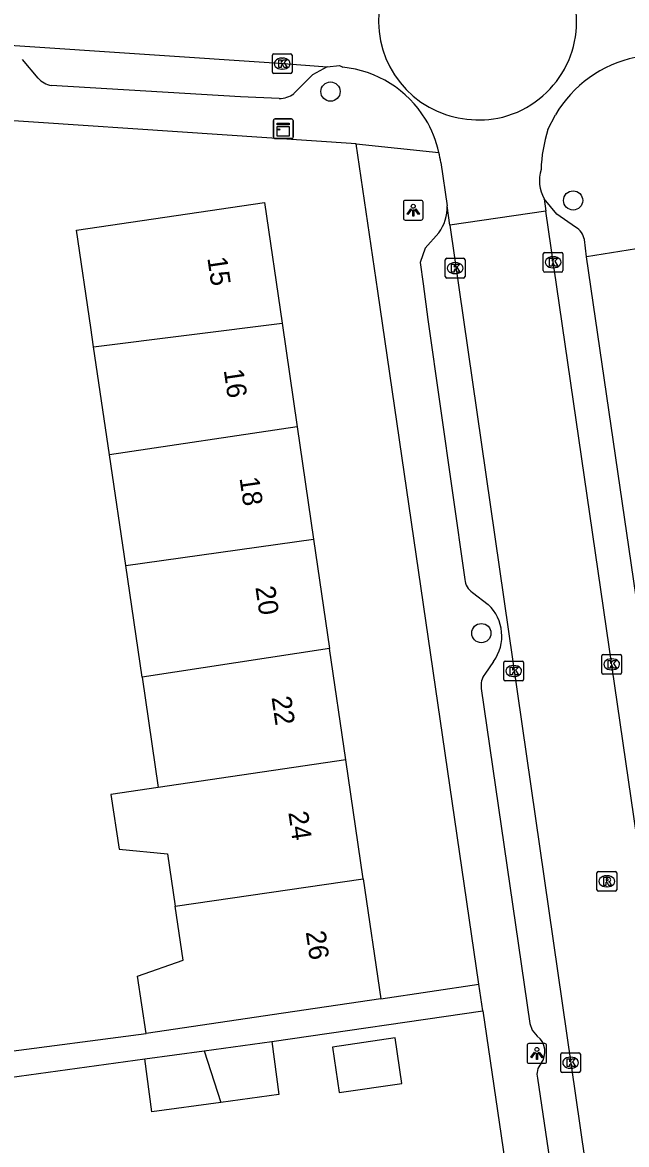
# Model space of a CAD drawing. Extents: x 159053 to 160041, y 380450 to 381422.
# Drawn here: x 159474.1 to 159504.8, y 381120.2 to 381177.1 of the extents above; entities that cross this region are included whole.
import ezdxf

# ---------------------------------------------------------------- set-up
doc = ezdxf.new("R2010")
doc.units = 0
for name, color, linetype in [('IMGEO_Boom', 7, 'Continuous'), ('IMGEO_Kast', 7, 'Continuous'), ('IMGEO_Kolk', 7, 'Continuous'), ('IMGEO_Lichtpunt', 7, 'Continuous'), ('IMGEO_Pand', 7, 'Continuous'), ('IMGEO_Pand_nummerreeks', 7, 'Continuous'), ('IMGEO_Rijbaan_lokaal_open', 7, 'Continuous'), ('IMGEO_Rioolput', 7, 'Continuous'), ('IMGEO_Voetpad_open', 7, 'Continuous')]:
    doc.layers.add(name, color=color, linetype=linetype)

msp = doc.modelspace()

# ---------------------------------------------------------------- linework, layer by layer
at = {"layer": 'IMGEO_Boom'}
for centre in [(159489.765, 381173.623), (159502.088, 381168.096), (159497.428, 381146.127)]:
    msp.add_circle(centre, 0.489, dxfattribs=at)
at = {"layer": 'IMGEO_Kast'}
for p, q in [((159486.868, 381171.309), (159486.868, 381172.15)), ((159486.868, 381172.15), (159486.868, 381171.309)), ((159486.943, 381172.234), (159487.784, 381172.234)), ((159487.784, 381172.234), (159486.943, 381172.234)), ((159487.868, 381172.159), (159487.868, 381171.318)), ((159487.868, 381171.318), (159487.868, 381172.159)), ((159487.793, 381171.234), (159486.952, 381171.234)), ((159486.952, 381171.234), (159487.793, 381171.234))]:
    msp.add_line(p, q, dxfattribs=at)
for points in [[(159487.063, 381172.024), (159487.663, 381172.024), (159487.663, 381171.939), (159487.063, 381171.939), (159487.063, 381172.024)], [(159487.063, 381171.849), (159487.663, 381171.849), (159487.663, 381171.36), (159487.063, 381171.36), (159487.063, 381171.849)]]:
    msp.add_lwpolyline(points, dxfattribs=at)
msp.add_circle((159487.147, 381171.698), 0.0377, dxfattribs=at)
for centre, start, end in [((159486.946, 381172.156), 92.4484, 184.2845), ((159486.946, 381172.156), 92.4484, 184.2845), ((159487.79, 381172.156), 2.4484, 94.2845), ((159487.79, 381172.156), 2.4484, 94.2845), ((159486.946, 381171.312), 182.4484, 274.2845), ((159486.946, 381171.312), 182.4484, 274.2845), ((159487.79, 381171.312), 272.4484, 4.2845), ((159487.79, 381171.312), 272.4484, 4.2845)]:
    msp.add_arc(centre, 0.0779, start, end, dxfattribs=at)
at = {"layer": 'IMGEO_Kolk'}
for p, q in [((159486.812, 381174.617), (159486.812, 381175.469)), ((159486.887, 381175.543), (159487.739, 381175.543)), ((159487.3, 381175.323), (159487.325, 381175.323)), ((159487.813, 381175.469), (159487.813, 381174.617)), ((159487.323, 381174.763), (159487.298, 381174.763)), ((159487.739, 381174.543), (159486.887, 381174.543)), ((159495.597, 381164.232), (159495.597, 381165.084)), ((159495.672, 381165.158), (159496.524, 381165.158)), ((159496.598, 381165.084), (159496.598, 381164.232)), ((159500.572, 381164.531), (159500.572, 381165.383)), ((159500.647, 381165.457), (159501.499, 381165.457)), ((159501.06, 381165.237), (159501.085, 381165.237)), ((159501.573, 381165.383), (159501.573, 381164.531)), ((159496.085, 381164.938), (159496.11, 381164.938)), ((159501.083, 381164.677), (159501.058, 381164.677)), ((159496.524, 381164.158), (159495.672, 381164.158)), ((159496.108, 381164.378), (159496.083, 381164.378)), ((159501.499, 381164.457), (159500.647, 381164.457)), ((159498.569, 381143.777), (159498.569, 381144.629)), ((159498.644, 381144.703), (159499.496, 381144.703)), ((159499.57, 381144.629), (159499.57, 381143.777)), ((159503.547, 381144.116), (159503.547, 381144.968)), ((159503.622, 381145.042), (159504.474, 381145.042)), ((159504.035, 381144.822), (159504.06, 381144.822)), ((159504.548, 381144.968), (159504.548, 381144.116)), ((159499.057, 381144.483), (159499.082, 381144.483)), ((159504.474, 381144.042), (159503.622, 381144.042)), ((159504.058, 381144.262), (159504.033, 381144.262)), ((159499.496, 381143.703), (159498.644, 381143.703)), ((159499.08, 381143.923), (159499.055, 381143.923)), ((159501.458, 381123.888), (159501.458, 381124.74)), ((159501.533, 381124.814), (159502.385, 381124.814)), ((159501.946, 381124.594), (159501.971, 381124.594)), ((159502.459, 381124.74), (159502.459, 381123.888)), ((159501.969, 381124.034), (159501.944, 381124.034)), ((159502.385, 381123.814), (159501.533, 381123.814))]:
    msp.add_line(p, q, dxfattribs=at)
for points in [[(159486.812, 381174.617), (159486.812, 381175.469)], [(159486.887, 381175.543), (159487.739, 381175.543)], [(159487.813, 381175.469), (159487.813, 381174.617)], [(159487.133, 381175.243), (159487.256, 381175.243), (159487.256, 381175.092), (159487.386, 381175.243), (159487.55, 381175.243), (159487.404, 381175.092), (159487.557, 381174.843), (159487.405, 381174.843), (159487.32, 381175.007), (159487.256, 381174.94), (159487.256, 381174.843), (159487.133, 381174.843), (159487.133, 381175.243)], [(159487.739, 381174.543), (159486.887, 381174.543)], [(159495.597, 381164.232), (159495.597, 381165.084)], [(159495.672, 381165.158), (159496.524, 381165.158)], [(159496.598, 381165.084), (159496.598, 381164.232)], [(159500.572, 381164.531), (159500.572, 381165.383)], [(159500.647, 381165.457), (159501.499, 381165.457)], [(159500.893, 381165.157), (159501.016, 381165.157), (159501.016, 381165.006), (159501.146, 381165.157), (159501.31, 381165.157), (159501.164, 381165.006), (159501.317, 381164.757), (159501.165, 381164.757), (159501.08, 381164.921), (159501.016, 381164.854), (159501.016, 381164.757), (159500.893, 381164.757), (159500.893, 381165.157)], [(159501.573, 381165.383), (159501.573, 381164.531)], [(159495.918, 381164.858), (159496.041, 381164.858), (159496.041, 381164.707), (159496.171, 381164.858), (159496.335, 381164.858), (159496.189, 381164.707), (159496.342, 381164.458), (159496.19, 381164.458), (159496.105, 381164.622), (159496.041, 381164.555), (159496.041, 381164.458), (159495.918, 381164.458), (159495.918, 381164.858)], [(159496.524, 381164.158), (159495.672, 381164.158)], [(159501.499, 381164.457), (159500.647, 381164.457)], [(159498.569, 381143.777), (159498.569, 381144.629)], [(159498.644, 381144.703), (159499.496, 381144.703)], [(159499.57, 381144.629), (159499.57, 381143.777)], [(159503.547, 381144.116), (159503.547, 381144.968)], [(159503.622, 381145.042), (159504.474, 381145.042)], [(159503.868, 381144.742), (159503.991, 381144.742), (159503.991, 381144.591), (159504.121, 381144.742), (159504.285, 381144.742), (159504.139, 381144.591), (159504.292, 381144.342), (159504.14, 381144.342), (159504.055, 381144.506), (159503.991, 381144.439), (159503.991, 381144.342), (159503.868, 381144.342), (159503.868, 381144.742)], [(159504.548, 381144.968), (159504.548, 381144.116)], [(159498.89, 381144.403), (159499.013, 381144.403), (159499.013, 381144.252), (159499.143, 381144.403), (159499.307, 381144.403), (159499.161, 381144.252), (159499.314, 381144.003), (159499.162, 381144.003), (159499.077, 381144.167), (159499.013, 381144.1), (159499.013, 381144.003), (159498.89, 381144.003), (159498.89, 381144.403)], [(159504.474, 381144.042), (159503.622, 381144.042)], [(159499.496, 381143.703), (159498.644, 381143.703)], [(159501.458, 381123.888), (159501.458, 381124.74)], [(159501.533, 381124.814), (159502.385, 381124.814)], [(159502.459, 381124.74), (159502.459, 381123.888)], [(159501.779, 381124.514), (159501.902, 381124.514), (159501.902, 381124.363), (159502.032, 381124.514), (159502.196, 381124.514), (159502.05, 381124.363), (159502.203, 381124.114), (159502.051, 381124.114), (159501.966, 381124.278), (159501.902, 381124.211), (159501.902, 381124.114), (159501.779, 381124.114), (159501.779, 381124.514)], [(159502.385, 381123.814), (159501.533, 381123.814)]]:
    msp.add_lwpolyline(points, dxfattribs=at)
for centre, start, end in [((159486.889, 381175.467), 91.552, 178.448), ((159486.889, 381175.467), 91.552, 178.448), ((159487.737, 381175.467), 1.552, 88.448), ((159487.737, 381175.467), 1.552, 88.448), ((159486.889, 381174.619), 181.552, 268.448), ((159486.889, 381174.619), 181.552, 268.448), ((159487.737, 381174.619), 271.552, 358.448), ((159487.737, 381174.619), 271.552, 358.448), ((159495.674, 381165.082), 91.552, 178.448), ((159495.674, 381165.082), 91.552, 178.448), ((159496.522, 381165.082), 1.552, 88.448), ((159496.522, 381165.082), 1.552, 88.448), ((159500.649, 381165.381), 91.552, 178.448), ((159500.649, 381165.381), 91.552, 178.448), ((159501.497, 381165.381), 1.552, 88.448), ((159501.497, 381165.381), 1.552, 88.448), ((159500.649, 381164.533), 181.552, 268.448), ((159500.649, 381164.533), 181.552, 268.448), ((159501.497, 381164.533), 271.552, 358.448), ((159501.497, 381164.533), 271.552, 358.448), ((159495.674, 381164.234), 181.552, 268.448), ((159495.674, 381164.234), 181.552, 268.448), ((159496.522, 381164.234), 271.552, 358.448), ((159496.522, 381164.234), 271.552, 358.448), ((159498.646, 381144.627), 91.552, 178.448), ((159498.646, 381144.627), 91.552, 178.448), ((159499.494, 381144.627), 1.552, 88.448), ((159499.494, 381144.627), 1.552, 88.448), ((159503.624, 381144.966), 91.552, 178.448), ((159503.624, 381144.966), 91.552, 178.448), ((159504.472, 381144.966), 1.552, 88.448), ((159504.472, 381144.966), 1.552, 88.448), ((159503.624, 381144.118), 181.552, 268.448), ((159503.624, 381144.118), 181.552, 268.448), ((159504.472, 381144.118), 271.552, 358.448), ((159504.472, 381144.118), 271.552, 358.448), ((159498.646, 381143.779), 181.552, 268.448), ((159498.646, 381143.779), 181.552, 268.448), ((159499.494, 381143.779), 271.552, 358.448), ((159499.494, 381143.779), 271.552, 358.448), ((159501.535, 381124.738), 91.552, 178.448), ((159501.535, 381124.738), 91.552, 178.448), ((159502.383, 381124.738), 1.552, 88.448), ((159502.383, 381124.738), 1.552, 88.448), ((159501.535, 381123.89), 181.552, 268.448), ((159501.535, 381123.89), 181.552, 268.448), ((159502.383, 381123.89), 271.552, 358.448), ((159502.383, 381123.89), 271.552, 358.448)]:
    msp.add_arc(centre, 0.0765, start, end, dxfattribs=at)
for centre, major_axis, ratio, start_param, end_param in [((159487.299, 381175.043), (-0.387, 0.002), 0.722429, 4.712389, 7.853982), ((159487.324, 381175.043), (-0.39, 0.002), 0.717154, 1.570796, 4.712389), ((159501.059, 381164.957), (-0.387, 0.002), 0.722429, 4.712389, 7.853982), ((159501.084, 381164.957), (-0.39, 0.002), 0.717154, 1.570796, 4.712389), ((159496.084, 381164.658), (-0.387, 0.002), 0.722429, 4.712389, 7.853982), ((159496.109, 381164.658), (-0.39, 0.002), 0.717154, 1.570796, 4.712389), ((159504.034, 381144.542), (-0.387, 0.002), 0.722429, 4.712389, 7.853982), ((159504.059, 381144.542), (-0.39, 0.002), 0.717154, 1.570796, 4.712389), ((159499.056, 381144.203), (-0.387, 0.002), 0.722429, 4.712389, 7.853982), ((159499.081, 381144.203), (-0.39, 0.002), 0.717154, 1.570796, 4.712389), ((159501.945, 381124.314), (-0.387, 0.002), 0.722429, 4.712389, 7.853982), ((159501.97, 381124.314), (-0.39, 0.002), 0.717154, 1.570796, 4.712389)]:
    msp.add_ellipse(centre, major_axis=major_axis, ratio=ratio, start_param=start_param, end_param=end_param, dxfattribs=at)
at = {"layer": 'IMGEO_Lichtpunt'}
for p, q in [((159493.469, 381168.003), (159493.469, 381167.196)), ((159493.469, 381168.003), (159493.469, 381167.196)), ((159494.371, 381168.098), (159493.563, 381168.098)), ((159494.371, 381168.098), (159493.563, 381168.098)), ((159494.465, 381167.196), (159494.465, 381168.003)), ((159494.465, 381167.196), (159494.465, 381168.003)), ((159493.563, 381167.102), (159494.371, 381167.102)), ((159493.563, 381167.102), (159494.371, 381167.102)), ((159499.748, 381125.19), (159499.748, 381124.383)), ((159499.748, 381125.19), (159499.748, 381124.383)), ((159500.65, 381125.285), (159499.842, 381125.285)), ((159500.65, 381125.285), (159499.842, 381125.285)), ((159500.744, 381124.383), (159500.744, 381125.19)), ((159500.744, 381124.383), (159500.744, 381125.19)), ((159499.842, 381124.289), (159500.65, 381124.289)), ((159499.842, 381124.289), (159500.65, 381124.289))]:
    msp.add_line(p, q, dxfattribs=at)
for points in [[(159493.843, 381167.667), (159493.882, 381167.639), (159493.694, 381167.377), (159493.656, 381167.404), (159493.843, 381167.667)], [(159493.945, 381167.619), (159493.992, 381167.619), (159493.992, 381167.297), (159493.945, 381167.297), (159493.945, 381167.619)], [(159494.055, 381167.639), (159494.093, 381167.666), (159494.28, 381167.404), (159494.241, 381167.376), (159494.055, 381167.639)], [(159500.122, 381124.854), (159500.161, 381124.826), (159499.973, 381124.564), (159499.935, 381124.591), (159500.122, 381124.854)], [(159500.224, 381124.806), (159500.271, 381124.806), (159500.271, 381124.484), (159500.224, 381124.484), (159500.224, 381124.806)], [(159500.334, 381124.826), (159500.372, 381124.853), (159500.559, 381124.591), (159500.52, 381124.563), (159500.334, 381124.826)]]:
    msp.add_lwpolyline(points, dxfattribs=at)
for centre in [(159493.968, 381167.801), (159500.247, 381124.988)]:
    msp.add_circle(centre, 0.0994, dxfattribs=at)
for centre, start, end in [((159493.563, 381168.003), 90, 180), ((159493.563, 381168.003), 90, 180), ((159494.371, 381168.003), 0, 90), ((159494.371, 381168.003), 0, 90), ((159493.563, 381167.196), 180, 270), ((159493.563, 381167.196), 180, 270), ((159494.371, 381167.196), 270, 0), ((159494.371, 381167.196), 270, 360), ((159499.842, 381125.19), 90, 180), ((159499.842, 381125.19), 90, 180), ((159500.65, 381125.19), 0, 90), ((159500.65, 381125.19), 0, 90), ((159499.842, 381124.383), 180, 270), ((159499.842, 381124.383), 180, 270), ((159500.65, 381124.383), 270, 0), ((159500.65, 381124.383), 270, 360)]:
    msp.add_arc(centre, 0.0946, start, end, dxfattribs=at)
at = {"layer": 'IMGEO_Pand'}
for points in [[(159477.731, 381160.668), (159477.587, 381161.646), (159476.861, 381166.592), (159486.412, 381167.988), (159487.308, 381161.857)], [(159477.731, 381160.668), (159487.308, 381161.857)], [(159487.308, 381161.857), (159488.076, 381156.599)], [(159478.537, 381155.178), (159477.731, 381160.668)], [(159488.076, 381156.599), (159478.537, 381155.178)], [(159488.076, 381156.599), (159488.908, 381150.9)], [(159479.362, 381149.557), (159478.537, 381155.178)], [(159479.362, 381149.557), (159488.908, 381150.9)], [(159488.908, 381150.9), (159489.72, 381145.339)], [(159480.194, 381143.889), (159479.362, 381149.557)], [(159489.72, 381145.339), (159480.194, 381143.889)], [(159490.544, 381139.699), (159489.72, 381145.339)], [(159480.194, 381143.889), (159481.016, 381138.293)], [(159490.544, 381139.699), (159481.016, 381138.293)], [(159491.427, 381133.657), (159490.544, 381139.699)], [(159481.016, 381138.293), (159478.614, 381137.938), (159479.023, 381135.154), (159481.483, 381134.919), (159481.873, 381132.261)], [(159481.873, 381132.261), (159491.427, 381133.657)], [(159491.427, 381133.657), (159492.317, 381127.564)], [(159480.395, 381125.804), (159479.97, 381128.703), (159482.276, 381129.517), (159481.873, 381132.261)], [(159492.317, 381127.564), (159487.371, 381126.834), (159480.395, 381125.804)], [(159483.342, 381124.914), (159486.781, 381125.383)], [(159486.781, 381125.383), (159487.147, 381122.694), (159484.195, 381122.292)], [(159489.871, 381125.11), (159490.212, 381122.797), (159493.39, 381123.266), (159493.049, 381125.579), (159489.871, 381125.11)], [(159480.328, 381124.503), (159483.342, 381124.914)], [(159483.342, 381124.914), (159484.195, 381122.292)], [(159484.195, 381122.292), (159480.695, 381121.815), (159480.328, 381124.503)]]:
    msp.add_lwpolyline(points, dxfattribs=at)
at = {"layer": 'IMGEO_Rijbaan_lokaal_open'}
for points in [[(159371.374, 381182.825), (159487.158, 381175.068), (159489.604, 381174.872)], [(159489.604, 381174.872), (159490.216, 381174.956), (159490.385, 381174.858)], [(159500.805, 381171.695), (159501.186, 381172.449)], [(159495.363, 381170.026), (159495.688, 381167.819)], [(159500.612, 381168.186), (159500.704, 381167.556)], [(159495.83, 381166.836), (159495.688, 381167.819)], [(159500.704, 381167.556), (159495.83, 381166.836)], [(159509.667, 381105.969), (159500.704, 381167.556)], [(159495.83, 381166.836), (159504.739, 381105.188)]]:
    msp.add_lwpolyline(points, dxfattribs=at)
for centre, radius, start, end in [((159497.254, 381177.183), 5.014, 305.472, 36.7465), ((159497.215, 381177.2), 5.004, 152.7452, 240.9291), ((159506.53, 381169.274), 6.216, 101.9456, 149.2819), ((159489.85, 381169.327), 5.556, 31.4566, 84.4763), ((159497.245, 381177.206), 5.038, 281.643, 305.407), ((159497.307, 381177.465), 5.28, 241.45, 280.417), ((159489.824, 381169.316), 5.585, 12.6069, 31.4156), ((159508.158, 381169.394), 7.704, 162.6237, 178.0228), ((159489.348, 381169.237), 6.067, 7.4772, 12.3589), ((159502.246, 381169.102), 1.873, 162.6559, 209.2731)]:
    msp.add_arc(centre, radius, start, end, dxfattribs=at)
at = {"layer": 'IMGEO_Rioolput'}
for p, q in [((159503.3, 381133.099), (159503.3, 381133.951)), ((159503.375, 381134.025), (159504.227, 381134.025)), ((159503.788, 381133.805), (159503.813, 381133.805)), ((159504.301, 381133.951), (159504.301, 381133.099)), ((159503.811, 381133.245), (159503.786, 381133.245)), ((159504.227, 381133.025), (159503.375, 381133.025))]:
    msp.add_line(p, q, dxfattribs=at)
for points in [[(159503.3, 381133.099), (159503.3, 381133.951)], [(159503.375, 381134.025), (159504.227, 381134.025)], [(159503.889, 381133.723), (159503.637, 381133.725), (159503.637, 381133.325)], [(159504.301, 381133.951), (159504.301, 381133.099)], [(159503.637, 381133.325), (159503.761, 381133.325), (159503.761, 381133.487), (159503.772, 381133.487)], [(159503.815, 381133.644), (159503.761, 381133.644), (159503.761, 381133.563)], [(159503.761, 381133.563), (159503.813, 381133.563)], [(159503.819, 381133.458), (159503.89, 381133.325), (159504.03, 381133.325), (159503.965, 381133.451)], [(159504.227, 381133.025), (159503.375, 381133.025)]]:
    msp.add_lwpolyline(points, dxfattribs=at)
for centre, radius, start, end in [((159503.377, 381133.949), 0.0765, 91.552, 178.448), ((159503.377, 381133.949), 0.0765, 91.552, 178.448), ((159503.888, 381133.613), 0.109, 350.3612, 89.416), ((159504.225, 381133.949), 0.0765, 1.552, 88.448), ((159504.225, 381133.949), 0.0765, 1.552, 88.448), ((159503.771, 381133.434), 0.0533, 26.0293, 88.6989), ((159503.797, 381133.752), 0.19, 274.7715, 282.9687), ((159503.821, 381133.548), 0.0964, 77.0061, 93.1865), ((159503.835, 381133.605), 0.0378, 276.6634, 79.6772), ((159503.886, 381133.613), 0.112, 277.5842, 350.9817), ((159503.87, 381133.398), 0.108, 29.5134, 73.7905), ((159503.377, 381133.101), 0.0765, 181.552, 268.448), ((159503.377, 381133.101), 0.0765, 181.552, 268.448), ((159504.225, 381133.101), 0.0765, 271.552, 358.448), ((159504.225, 381133.101), 0.0765, 271.552, 358.448)]:
    msp.add_arc(centre, radius, start, end, dxfattribs=at)
for centre, major_axis, ratio, start_param, end_param in [((159503.787, 381133.525), (-0.387, 0.002), 0.722429, 4.712389, 7.853982), ((159503.812, 381133.525), (-0.39, 0.002), 0.717154, 1.570796, 4.712389)]:
    msp.add_ellipse(centre, major_axis=major_axis, ratio=ratio, start_param=start_param, end_param=end_param, dxfattribs=at)
at = {"layer": 'IMGEO_Voetpad_open'}
for points in [[(159474.913, 381174.302), (159474.118, 381175.245)], [(159489.604, 381174.872), (159488.858, 381174.48), (159487.911, 381173.518)], [(159487.157, 381173.275), (159485.193, 381173.349), (159475.583, 381173.936)], [(159491.067, 381170.966), (159465.838, 381172.666)], [(159497.307, 381128.294), (159492.161, 381163.484), (159491.067, 381170.966)], [(159491.067, 381170.966), (159495.274, 381170.535)], [(159502.212, 381166.735), (159501.264, 381167.397), (159500.612, 381168.186)], [(159495.271, 381166.455), (159494.579, 381165.668), (159494.319, 381164.942), (159494.465, 381163.863), (159494.712, 381162.044), (159496.581, 381148.851)], [(159502.772, 381165.23), (159502.662, 381166.106)], [(159505.308, 381165.647), (159502.772, 381165.23)], [(159505.28, 381148.066), (159502.772, 381165.23)], [(159496.973, 381148.19), (159497.776, 381147.572)], [(159498.045, 381144.691), (159497.601, 381144.051)], [(159497.419, 381143.315), (159499.889, 381126.302), (159500, 381125.97), (159500.266, 381125.665)], [(159492.317, 381127.564), (159497.307, 381128.294)], [(159497.503, 381126.951), (159497.307, 381128.294)], [(159486.781, 381125.383), (159497.503, 381126.951)], [(159497.503, 381126.951), (159500, 381109.876), (159500.255, 381108.132)], [(159472.893, 381124.821), (159480.395, 381125.804)], [(159474.122, 381097.322), (159470.503, 381123.163), (159480.328, 381124.503)], [(159500.275, 381123.531), (159502.634, 381107.659)]]:
    msp.add_lwpolyline(points, dxfattribs=at)
for centre, radius, start, end in [((159475.778, 381175.09), 1.17, 222.3162, 260.391), ((159487.137, 381174.627), 1.353, 270.8346, 304.8917), ((159493.559, 381167.724), 2.131, 323.4463, 2.5549), ((159501.759, 381165.935), 0.919, 10.7021, 60.4594), ((159497.545, 381148.976), 0.972, 187.3918, 233.9475), ((159496.293, 381145.981), 2.175, 323.6417, 47.0268), ((159498.427, 381143.456), 1.018, 144.239, 187.9817), ((159499.649, 381124.869), 1.007, 323.1653, 52.2116), ((159501.035, 381123.734), 0.786, 137.492, 194.9504)]:
    msp.add_arc(centre, radius, start, end, dxfattribs=at)

# ---------------------------------------------------------------- texts
at = {"layer": 'IMGEO_Pand_nummerreeks'}
for s, rotation, p in [('15', 278.3108, (159483.507, 381165.176)), ('16', 278.3108, (159484.339, 381159.482)), ('18', 278.3108, (159485.14, 381154)), ('20', 278.3108, (159485.949, 381148.46)), ('22', 278.3134, (159486.768, 381142.866)), ('24', 278.3134, (159487.621, 381137.022)), ('26', 278.3104, (159488.507, 381130.954))]:
    msp.add_text(s, height=1, rotation=rotation, dxfattribs=at).set_placement(p)

doc.saveas('drawing.dxf')
